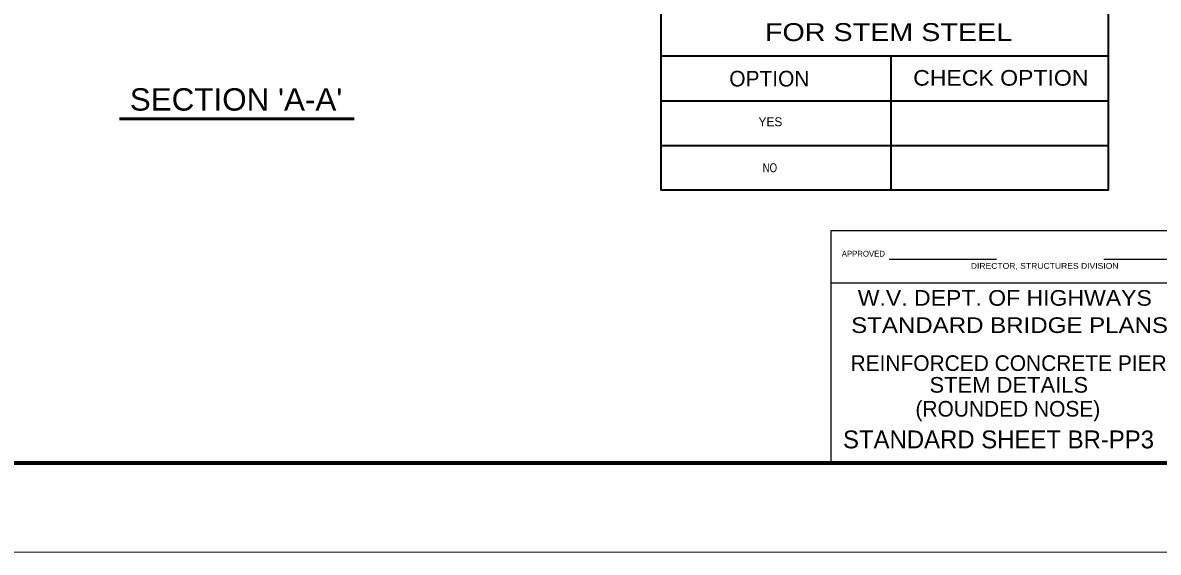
# Model space of a CAD drawing. Extents: x 3.64 to 6.84, y -0.8 to 1.19.
# Drawn here: x 4.986 to 6.045, y -0.795 to -0.301 of the extents above; entities that cross this region are included whole.
import ezdxf
from ezdxf.enums import TextEntityAlignment as Align

# ---------------------------------------------------------------- set-up
doc = ezdxf.new("R2010")
doc.units = 0
doc.header["$LTSCALE"] = 0.0033
doc.linetypes.add('DOTTED', pattern=[1.5, 0.3, -1.2])
doc.layers.add('1', color=7, linetype='Continuous', lineweight=40)

msp = doc.modelspace()

# ---------------------------------------------------------------- linework, layer by layer
at = {"layer": '1', "lineweight": 35}
for p, q in [((5.58125, -0.331917), (5.997917, -0.331917)), ((5.795583, -0.45725), (5.795583, -0.33225)), ((5.58125, -0.373583), (5.997917, -0.373583)), ((5.58125, -0.41525), (5.997917, -0.41525))]:
    msp.add_line(p, q, dxfattribs=at)
at = {"layer": '1', "lineweight": 53}
msp.add_line((5.0765, -0.390417), (5.29525, -0.390417), dxfattribs=at)
at = {"layer": '1', "linetype": 'DOTTED', "lineweight": 25}
msp.add_line((5.79375, -0.521417), (6.05975, -0.521417), dxfattribs=at)
at = {"layer": '1', "lineweight": 25}
msp.add_line((5.739917, -0.543333), (6.17325, -0.543333), dxfattribs=at)
at = {"layer": '1', "lineweight": 70}
msp.add_line((3.811583, -0.711333), (6.75825, -0.711333), dxfattribs=at)
at = {"layer": '1', "lineweight": 13}
msp.add_line((6.841583, -0.794667), (3.644833, -0.794667), dxfattribs=at)
at = {"layer": '1', "lineweight": 35}
msp.add_lwpolyline([(5.58125, -0.2515), (5.997917, -0.2515), (5.997917, -0.456917), (5.58125, -0.456917)], close=True, dxfattribs=at)
at = {"layer": '1'}
msp.add_lwpolyline([(3.811583, -0.711333), (6.17325, -0.711333), (6.17325, -0.38625), (6.75825, -0.38625)], dxfattribs=at)
at = {"layer": '1', "lineweight": 25}
msp.add_lwpolyline([(5.739917, -0.711333), (5.739917, -0.494583), (6.17325, -0.494583)], dxfattribs=at)

# ---------------------------------------------------------------- texts
at = {"layer": '1'}
for s, height, width, p in [('FOR STEM STEEL', 0.01667, 1.2, (5.79325, -0.318)), ('NO', 0.008334, 0.8, (5.682667, -0.44025))]:
    msp.add_text(s, height=height, dxfattribs=dict(at, width=width)).set_placement(p, align=Align.CENTER)
for s, height, p in [('OPTION', 0.01458, (5.644833, -0.360333)), ('APPROVED', 0.005417, (5.749667, -0.519)), ('REINFORCED CONCRETE PIER', 0.01458, (5.757833, -0.625583)), ('(ROUNDED NOSE)', 0.01458, (5.818333, -0.668167)), ('STANDARD SHEET BR-PP3', 0.01667, (5.750833, -0.69775))]:
    msp.add_text(s, height=height, dxfattribs=at).set_placement(p)
for s, height, width, p in [('CHECK OPTION', 0.01458, 1.1, (5.81625, -0.359583)), ("SECTION 'A-A'", 0.02083, 1.05, (5.086167, -0.382833)), ('DIRECTOR, STRUCTURES DIVISION', 0.005418, 1.1, (5.869917, -0.530333)), ('W.V. DEPT. OF HIGHWAYS', 0.01458, 1.1, (5.764583, -0.56475)), ('STANDARD BRIDGE PLANS', 0.01458, 1.15, (5.758417, -0.590167)), ('STEM DETAILS', 0.01458, 1.05, (5.831417, -0.645833))]:
    msp.add_text(s, height=height, dxfattribs=dict(at, width=width)).set_placement(p)
msp.add_text('YES', height=0.008334, dxfattribs=at).set_placement((5.683167, -0.397417), align=Align.CENTER)

doc.saveas('drawing.dxf')
